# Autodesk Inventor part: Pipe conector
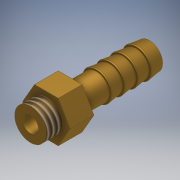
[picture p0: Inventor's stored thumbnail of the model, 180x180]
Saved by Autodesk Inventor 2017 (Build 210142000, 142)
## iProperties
Created: 2020-03
Part Number: Pipe conector
Material: Brass, Soft Yellow
Document SubType Name: Modeling
Designer: user
Density: 8.47 g/cm^3
Appearance: Brass - Satin
Author: user
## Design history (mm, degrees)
sketch "Sketch1"
  geometry: C1 r 1.5 at (0, 0); C2 r 3 at (0, 0); 1 further point
  constraints: 2 centre point, 2 coincident
  dimensions: "d0" = 3 diameter of C1; "d1" = 6 diameter of C2
extrude "Extrusion1" new body sketch "Sketch1" distance "d2" = 3; taper "d3" = 0 deg
sketch "Sketch2"
  geometry: L1 (-4.5, 0)-(-2.25, 3.897); L2 (-2.25, 3.897)-(2.25, 3.897); L3 (2.25, 3.897)-(4.5, 0); L4 (4.5, 0)-(2.25, -3.897); L5 (2.25, -3.897)-(-2.25, -3.897); L6 (-2.25, -3.897)-(-4.5, 0); 2 further points
  constraints: 12 end point, 1 coincident, 13 other
  dimensions: "d4" = 9 distance of L3.end L1.start
extrude "Extrusion2" join sketch "Sketch2" distance "d5" = 4.5; taper "d6" = 0 deg
sketch "Sketch3"
  geometry: C1 r 1.5 at (0, 0); 1 further point
  constraints: 1 centre point, 1 coincident
extrude "Extrusion3" cut sketch "Sketch3" distance "d7" = 4.5; taper "d8" = 0 deg
sketch "Sketch5"
  geometry: L1 (7.5, 1.5)-(7.5, -1.5) reference; L2 (7.5, 1.5)-(22.5, 1.5); L3 (22.5, 1.5)-(22.5, 2.5); L4 (22.5, 2.5)-(20.189, 2.812); L5 (19.964, 2.64)-(19.945, 2.5); L6 (19.945, 2.5)-(17.663, 2.808); L7 (17.436, 2.61)-(17.436, 2.5); L8 (17.436, 2.5)-(15.154, 2.808); L9 (14.927, 2.5)-(14.927, 2.61); L10 (14.927, 2.5)-(12.645, 2.808); L11 (12.418, 2.61)-(12.418, 2.5); L12 (12.418, 2.5)-(7.5, 2.5); L13 (7.5, 0)-(7.5, 3.897) reference; L14 (7.5, 2.5)-(7.5, 1.5); L15 (-4.5, 0)-(27, 0) reference; A1 r 0.2 centre (20.162, 2.614) between (20.189, 2.812) and (19.964, 2.64); A2 r 0.2 centre (17.636, 2.61) between (17.663, 2.808) and (17.436, 2.61); A3 r 0.2 centre (15.127, 2.61) between (15.154, 2.808) and (14.927, 2.61); A4 r 0.2 centre (12.618, 2.61) between (12.645, 2.808) and (12.418, 2.61); 1 further point
  constraints: 24 end point, 8 point on circle, 8 tangent, 4 centre point, 3 equal radius, 3 parallel, 3 vertical, 2 perpendicular, 1 collinear, 1 horizontal, 1 point on line
  dimensions: "d9" = 15 distance of L1.start L2.end; "d10" = 1 distance of L2.end L3.end; "d11" = 0.2 radius of A1
revolve "Revolution1" sketch "Sketch5" stored, may be unused: angle "d12" = 90 deg
thread "Thread1" dims "d13" = 10, "d14" = 0
body "Solid1"
